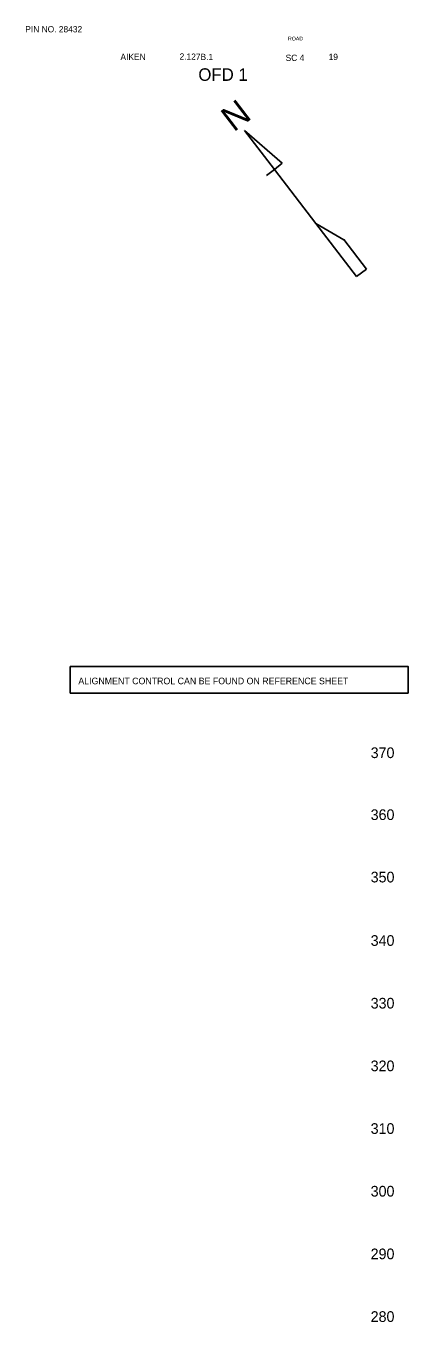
# Model space of a CAD drawing. Extents: x 50962 to 52632, y 49593 to 50638.
# Drawn here: x 52328 to 52632, y 49603 to 50637 of the extents above; entities that cross this region are included whole.
import ezdxf

# ---------------------------------------------------------------- set-up
doc = ezdxf.new("R2010")
doc.units = 0
for name, color, linetype in [('Level 1', 7, 'Continuous'), ('Level 2', 7, 'Continuous'), ('Level 25', 7, 'Continuous'), ('Level 42', 7, 'Continuous')]:
    doc.layers.add(name, color=color, linetype=linetype)

msp = doc.modelspace()

# ---------------------------------------------------------------- linework, layer by layer
at = {"layer": 'Level 2'}
for p, q in [((52532, 50527.7), (52501.9, 50554)), ((52501.9, 50554), (52501.9, 50554)), ((52501.9, 50554), (52525.8, 50522.9)), ((52525.8, 50522.9), (52532, 50527.7)), ((52532, 50527.7), (52531.7, 50528.1)), ((52519.6, 50518.1), (52525.8, 50522.9)), ((52558.9, 50479.7), (52525.8, 50522.9)), ((52581.3, 50466.7), (52558.9, 50479.7)), ((52558.9, 50479.7), (52591.4, 50437.4)), ((52599.2, 50443.3), (52581.1, 50466.9)), ((52581.1, 50466.9), (52581.3, 50466.7)), ((52591.4, 50437.4), (52599.2, 50443.3))]:
    msp.add_line(p, q, dxfattribs=at)
at = {"layer": 'Level 25'}
msp.add_lwpolyline([(52363.1, 50126.3), (52632.4, 50126.3), (52632.4, 50105), (52363.1, 50105)], close=True, dxfattribs=at)

# ---------------------------------------------------------------- texts
at = {"layer": 'Level 1'}
for s, height, p in [('PIN NO. 28432', 5, (52327.2, 50632.2)), ('ROAD', 3, (52536.7, 50625.7)), ('AIKEN', 5, (52403.1, 50610.1)), ('SC 4', 5, (52534.8, 50609.4)), ('19', 5, (52569.1, 50610.1)), ('OFD 1', 10, (52465.2, 50593.5))]:
    msp.add_text(s, height=height, dxfattribs=at).set_placement(p)
msp.add_text(' 2.127B.1', height=5, rotation=359, dxfattribs=at).set_placement((52448.3, 50610.5))
at = {"layer": 'Level 2'}
msp.add_text('N', height=20, rotation=37.4768, dxfattribs=at).set_placement((52493.4, 50552.2))
at = {"layer": 'Level 25'}
msp.add_text('ALIGNMENT CONTROL CAN BE FOUND ON REFERENCE SHEET', height=5.25, dxfattribs=at).set_placement((52369.5, 50112.1))
at = {"layer": 'Level 42'}
for s, p in [('370', (52602.6, 50053.2)), ('360', (52602.6, 50003.8)), ('350', (52602.6, 49954)), ('340', (52602.6, 49903.4)), ('330', (52602.6, 49853.4)), ('320', (52602.6, 49803.4)), ('310', (52602.6, 49753.4)), ('300', (52602.6, 49703.4)), ('290', (52602.6, 49653.4)), ('280', (52602.6, 49603.4))]:
    msp.add_text(s, height=8.5, dxfattribs=at).set_placement(p)

doc.saveas('drawing.dxf')
